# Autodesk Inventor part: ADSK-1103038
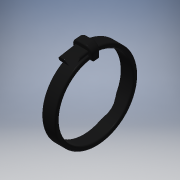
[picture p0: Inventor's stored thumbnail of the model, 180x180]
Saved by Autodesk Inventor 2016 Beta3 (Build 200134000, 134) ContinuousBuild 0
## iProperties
Shininess: 41.0
Length Units: 11272
Angle Units: 11279
Time Units: 11290
Mass Units: 11286
Length Display Precision: 4
Angle Display Precision: 2
Compacted: True
Created: 2000-08
Part Number: ADSK-1103038
Document SubType Name: Modeling
Description: METAL TIE
Mass: 0.127833 g
Surface Area: 3.35412 cm^2
Volume: 0.113127 cm^3
Density: 1.13 g/cm^3
Material: Nylon-6/6
Appearance: Glossy - Black
Density: 0.0
Volumn: 0.0
Area: 0.0
PropertySet Name: Model Information
Control State: 0
Master: False
Checked Out: False
Author: Autodesk, Inc.
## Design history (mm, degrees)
node "Revolution1" dims "d3" = 270 deg
  sketch "Sketch3"
    geometry: L1 (-13.841, 6.211)-(-11.301, 6.211); L2 (-11.301, 6.211)-(-11.301, 5.365); L3 (-11.301, 5.365)-(-13.841, 5.365); L4 (-13.841, 5.365)-(-13.841, 6.211); L5 (-15.021, -1.62)-(-10.408, -1.62)
    constraints: 10 end point, 2 parallel, 2 perpendicular, 1 horizontal
    dimensions: "d0" = 2.54 distance of L1.start L1.end; "d1" = 0.84667 distance between parallel lines of L1 L3 (= 0.333333 x d0); "d2" = 13.97 diameter of L3 L5
workaxis "Work Axis1"
node "Revolution2" dims "d5" = 90 deg
  sketch "Sketch4"
    geometry: L1 (0, 0)-(2.54, 0) reference; L2 (0, -0.847)-(0, 0) reference; L3 (2.54, -0.847)-(0, -0.847) reference; L4 (2.54, 0)-(2.54, -0.847) reference; L5 (-1.305, -8.467)-(3.845, -8.467)
    constraints: 2 end point, 1 perpendicular
    dimensions: "d4" = 7.62 distance between parallel lines of L3 L5
node "Revolution3" dims "d6" = 10 deg
  sketch "Sketch5"
    geometry: L1 (2.54, 0.608)-(0, 0.608) reference; L2 (0, 0)-(0, 0.608) reference; L3 (2.54, 0)-(0, 0) reference; L4 (2.54, 0.608)-(2.54, 0) reference; L5 (-0.661, 0)-(3.094, 0); L6 (3.094, 0)-(3.094, 2.551); L7 (3.094, 2.551)-(-0.661, 2.551); L8 (-0.661, 2.551)-(-0.661, 0); L9 (3.845, -6.985)-(-1.412, -6.985) reference
    constraints: 8 end point, 2 parallel, 1 horizontal, 1 perpendicular
node "Fillet1" dims "d7" = 1.27
node "Extrusion1" dims "d8" = 3.175, "d9" = 0
  sketch "Sketch6"
    geometry: L1 (0, 0.18)-(2.524, 0.18); L2 (2.524, 0.18)-(2.524, 0.866); L3 (2.524, 0.866)-(0, 0.866); L4 (0, 0.866)-(0, 0.18)
    constraints: 8 end point, 2 parallel, 1 horizontal, 1 perpendicular
node "Fillet2" dims "d10" = 0.254
node "Fillet3" dims "d11" = 0.254
node "Fillet4" dims "d12" = 0.254
body "Solid1"
